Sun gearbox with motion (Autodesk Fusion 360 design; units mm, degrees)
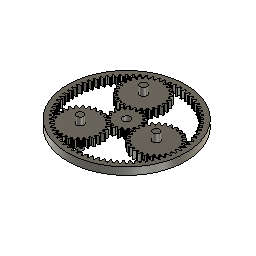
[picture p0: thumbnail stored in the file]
description: Spur Gear; Module: 2.0; Num Teeth: 72; Pressure Angle: 20.0; Backlash: 0.20 mm
description: Spur Gear; Module: 2.0; Num Teeth: 27; Pressure Angle: 20.0; Backlash: 0.20 mm
description: Spur Gear; Module: 2.0; Num Teeth: 18; Pressure Angle: 20.0; Backlash: 0.20 mm
sketch "Base Circle" plane through (0, 0, 0) normal (0, 0, 1) x axis (1, 0, 0)
  circle C1 centre (0, 0) radius 69.686
  circle C2 centre (0, 0) radius 5
extrude "Extrude1" new body sketch "Base Circle" along normal blind 10
sketch "Gear Tooth" plane through (0, 0, 0) normal (0, 0, 1) x axis (1, 0, 0)
  curve K1 (73.9963, -0.7431) -> (67.614, -2.437)
  curve K2 (73.9963, 0.7431) -> (67.614, 2.437)
  line L1 (67.614, -2.437) -> (67.614, 2.437)
  arc A1 centre (0, 0) radius 74 clockwise from (73.9963, 0.7431) to (73.9963, -0.7431)
extrude "Extrude2" add sketch "Gear Tooth" along normal blind 10
fillet "Fillet1" radius 1
circular_pattern "C-Pattern1" countU 72 TotalAngle 360
sketch "Diametrial Pitch Circle" plane through (0, 0, 0) normal (0, 0, 1) x axis (1, 0, 0)
  circle C1 centre (0, 0) radius 72
sketch "Sketch1" plane through (0, 0, 10) normal (0, 0, 1) x axis (-1, 0, 0)
  curve K1 (-69.6244, 2.9297) -> (-70.3744, 2.0033)
  curve K2 (-73.9963, 0.7431) -> (-70.3744, 2.0033)
  curve K3 (-70.3744, -2.0033) -> (-73.9963, -0.7431)
  curve K4 (-70.3744, -2.0033) -> (-69.6244, -2.9297)
  curve K5 (-69.6148, -3.1496) -> (-70.2812, -4.1379)
  curve K6 (-73.7795, -5.709) -> (-70.2812, -4.1379)
  curve K7 (-69.932, -8.1292) -> (-73.6499, -7.1894)
  curve K8 (-69.932, -8.1292) -> (-69.1041, -8.9867)
  curve K9 (-69.0754, -9.2049) -> (-69.6531, -10.2475)
  curve K10 (-73.0011, -12.1176) -> (-69.6531, -10.2475)
  curve K11 (-68.9574, -14.1932) -> (-72.7431, -13.5811)
  curve K12 (-68.9574, -14.1932) -> (-68.0579, -14.9754)
  curve K13 (-68.0103, -15.1902) -> (-68.495, -16.2792)
  curve K14 (-71.6672, -18.4339) -> (-68.495, -16.2792)
  curve K15 (-67.458, -20.1493) -> (-71.2826, -19.8694)
  curve K16 (-67.458, -20.1493) -> (-66.4937, -20.85)
  curve K17 (-66.4275, -21.0599) -> (-66.8155, -22.187)
  curve K18 (-69.7879, -24.61) -> (-66.8155, -22.187)
  curve K19 (-65.4452, -25.9519) -> (-69.2796, -26.0065)
  curve K20 (-65.4452, -25.9519) -> (-64.4235, -26.566)
  curve K21 (-64.3393, -26.7693) -> (-64.6275, -27.9259)
  curve K22 (-67.3774, -30.5987) -> (-64.6275, -27.9259)
  curve K23 (-62.9343, -31.5571) -> (-66.7494, -31.9456)
  curve K24 (-62.9343, -31.5571) -> (-61.863, -32.0798)
  curve K25 (-61.7614, -32.275) -> (-61.9477, -33.4523)
  curve K26 (-64.4542, -36.3546) -> (-61.9477, -33.4523)
  curve K27 (-59.9444, -36.9221) -> (-63.7111, -37.6416)
  curve K28 (-59.9444, -36.9221) -> (-58.8316, -37.3494)
  curve K29 (-58.7134, -37.535) -> (-58.7964, -38.7241)
  curve K30 (-61.0404, -41.8338) -> (-58.7964, -38.7241)
  curve K31 (-56.4983, -42.0061) -> (-60.188, -43.0512)
  curve K32 (-56.4983, -42.0061) -> (-55.3525, -42.3348)
  curve K33 (-55.2186, -42.5094) -> (-55.1976, -43.7012)
  curve K34 (-57.1621, -46.9947) -> (-55.1976, -43.7012)
  curve K35 (-52.6222, -46.7704) -> (-56.2068, -48.1331)
  curve K36 (-52.6222, -46.7704) -> (-51.4522, -46.998)
  curve K37 (-51.3035, -47.1602) -> (-51.1788, -48.3457)
  curve K38 (-52.8487, -51.7978) -> (-51.1788, -48.3457)
  curve K39 (-48.3457, -51.1788) -> (-51.7978, -52.8487)
  curve K40 (-48.3457, -51.1788) -> (-47.1602, -51.3035)
  curve K41 (-46.998, -51.4522) -> (-46.7704, -52.6222)
  curve K42 (-48.1331, -56.2068) -> (-46.7704, -52.6222)
  curve K43 (-43.7012, -55.1976) -> (-46.9947, -57.1621)
  curve K44 (-43.7012, -55.1976) -> (-42.5094, -55.2186)
  curve K45 (-42.3348, -55.3525) -> (-42.0061, -56.4983)
  curve K46 (-43.0512, -60.188) -> (-42.0061, -56.4983)
  curve K47 (-38.7241, -58.7964) -> (-41.8338, -61.0404)
  curve K48 (-38.7241, -58.7964) -> (-37.535, -58.7134)
  curve K49 (-37.3494, -58.8316) -> (-36.9221, -59.9444)
  curve K50 (-37.6416, -63.7111) -> (-36.9221, -59.9444)
  curve K51 (-33.4523, -61.9477) -> (-36.3546, -64.4542)
  curve K52 (-33.4523, -61.9477) -> (-32.275, -61.7614)
  curve K53 (-32.0798, -61.863) -> (-31.5571, -62.9343)
  curve K54 (-31.9456, -66.7494) -> (-31.5571, -62.9343)
  curve K55 (-27.9259, -64.6275) -> (-30.5987, -67.3774)
  curve K56 (-27.9259, -64.6275) -> (-26.7693, -64.3393)
  curve K57 (-26.566, -64.4235) -> (-25.9519, -65.4452)
  curve K58 (-26.0065, -69.2796) -> (-25.9519, -65.4452)
  curve K59 (-22.187, -66.8155) -> (-24.61, -69.7879)
  curve K60 (-22.187, -66.8155) -> (-21.0599, -66.4275)
  curve K61 (-20.85, -66.4937) -> (-20.1493, -67.458)
  curve K62 (-19.8694, -71.2826) -> (-20.1493, -67.458)
  curve K63 (-16.2792, -68.495) -> (-18.4339, -71.6672)
  curve K64 (-16.2792, -68.495) -> (-15.1902, -68.0103)
  curve K65 (-14.9754, -68.0579) -> (-14.1932, -68.9574)
  curve K66 (-13.5811, -72.7431) -> (-14.1932, -68.9574)
  curve K67 (-10.2475, -69.6531) -> (-12.1176, -73.0011)
  curve K68 (-10.2475, -69.6531) -> (-9.2049, -69.0754)
  curve K69 (-8.9867, -69.1041) -> (-8.1292, -69.932)
  curve K70 (-7.1894, -73.6499) -> (-8.1292, -69.932)
  curve K71 (-4.1379, -70.2812) -> (-5.709, -73.7795)
  curve K72 (-4.1379, -70.2812) -> (-3.1496, -69.6148)
  curve K73 (-2.9297, -69.6244) -> (-2.0033, -70.3744)
  curve K74 (-0.7431, -73.9963) -> (-2.0033, -70.3744)
  curve K75 (2.0033, -70.3744) -> (0.7431, -73.9963)
  curve K76 (2.0033, -70.3744) -> (2.9297, -69.6244)
  curve K77 (3.1496, -69.6148) -> (4.1379, -70.2812)
  curve K78 (5.709, -73.7795) -> (4.1379, -70.2812)
  curve K79 (8.1292, -69.932) -> (7.1894, -73.6499)
  curve K80 (8.1292, -69.932) -> (8.9867, -69.1041)
  curve K81 (9.2049, -69.0754) -> (10.2475, -69.6531)
  curve K82 (12.1176, -73.0011) -> (10.2475, -69.6531)
  curve K83 (14.1932, -68.9574) -> (13.5811, -72.7431)
  curve K84 (14.1932, -68.9574) -> (14.9754, -68.0579)
  curve K85 (15.1902, -68.0103) -> (16.2792, -68.495)
  curve K86 (18.4339, -71.6672) -> (16.2792, -68.495)
  curve K87 (20.1493, -67.458) -> (19.8694, -71.2826)
  curve K88 (20.1493, -67.458) -> (20.85, -66.4937)
  curve K89 (21.0599, -66.4275) -> (22.187, -66.8155)
  curve K90 (24.61, -69.7879) -> (22.187, -66.8155)
  curve K91 (25.9519, -65.4452) -> (26.0065, -69.2796)
  curve K92 (25.9519, -65.4452) -> (26.566, -64.4235)
  curve K93 (26.7693, -64.3393) -> (27.9259, -64.6275)
  curve K94 (30.5987, -67.3774) -> (27.9259, -64.6275)
  curve K95 (31.5571, -62.9343) -> (31.9456, -66.7494)
  curve K96 (31.5571, -62.9343) -> (32.0798, -61.863)
  curve K97 (32.275, -61.7614) -> (33.4523, -61.9477)
  curve K98 (36.3546, -64.4542) -> (33.4523, -61.9477)
  curve K99 (36.9221, -59.9444) -> (37.6416, -63.7111)
  curve K100 (36.9221, -59.9444) -> (37.3494, -58.8316)
  curve K101 (37.535, -58.7134) -> (38.7241, -58.7964)
  curve K102 (41.8338, -61.0404) -> (38.7241, -58.7964)
  curve K103 (42.0061, -56.4983) -> (43.0512, -60.188)
  curve K104 (42.0061, -56.4983) -> (42.3348, -55.3525)
  curve K105 (42.5094, -55.2186) -> (43.7012, -55.1976)
  curve K106 (46.9947, -57.1621) -> (43.7012, -55.1976)
  curve K107 (46.7704, -52.6222) -> (48.1331, -56.2068)
  curve K108 (46.7704, -52.6222) -> (46.998, -51.4522)
  curve K109 (47.1602, -51.3035) -> (48.3457, -51.1788)
  curve K110 (51.7978, -52.8487) -> (48.3457, -51.1788)
  curve K111 (51.1788, -48.3457) -> (52.8487, -51.7978)
  curve K112 (51.1788, -48.3457) -> (51.3035, -47.1602)
  curve K113 (51.4522, -46.998) -> (52.6222, -46.7704)
  curve K114 (56.2068, -48.1331) -> (52.6222, -46.7704)
  curve K115 (55.1976, -43.7012) -> (57.1621, -46.9947)
  curve K116 (55.1976, -43.7012) -> (55.2186, -42.5094)
  curve K117 (55.3525, -42.3348) -> (56.4983, -42.0061)
  curve K118 (60.188, -43.0512) -> (56.4983, -42.0061)
  curve K119 (58.7964, -38.7241) -> (61.0404, -41.8338)
  curve K120 (58.7964, -38.7241) -> (58.7134, -37.535)
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  point P1 (0, 0)
  point P435 (0, 0)
  coincident P1 P435
  dimension "d9" diameter = 160
extrude "Extrude1" new body sketch "Sketch1" against normal blind 10
remove_instance "RemoveInstance1"
sketch "Sketch2" plane through (0, 0, 10) normal (0, 0, 1) x axis (-1, 0, 0)
  curve K1 (-70.3744, 2.0033) -> (-73.9963, 0.7431)
  curve K2 (-69.6244, 2.9297) -> (-70.3744, 2.0033)
  curve K3 (-70.2812, 4.1379) -> (-69.6148, 3.1496)
  curve K4 (-73.7795, 5.709) -> (-70.2812, 4.1379)
  curve K5 (-69.932, 8.1292) -> (-73.6499, 7.1894)
  curve K6 (-69.1041, 8.9867) -> (-69.932, 8.1292)
  curve K7 (-69.6531, 10.2475) -> (-69.0754, 9.2049)
  curve K8 (-73.0011, 12.1176) -> (-69.6531, 10.2475)
  curve K9 (-68.9574, 14.1932) -> (-72.7431, 13.5811)
  curve K10 (-68.0579, 14.9754) -> (-68.9574, 14.1932)
  curve K11 (-68.495, 16.2792) -> (-68.0103, 15.1902)
  curve K12 (-71.6672, 18.4339) -> (-68.495, 16.2792)
  curve K13 (-67.458, 20.1493) -> (-71.2826, 19.8694)
  curve K14 (-66.4937, 20.85) -> (-67.458, 20.1493)
  curve K15 (-66.8155, 22.187) -> (-66.4275, 21.0599)
  curve K16 (-69.7879, 24.61) -> (-66.8155, 22.187)
  curve K17 (-65.4452, 25.9519) -> (-69.2796, 26.0065)
  curve K18 (-64.4235, 26.566) -> (-65.4452, 25.9519)
  curve K19 (-64.6275, 27.9259) -> (-64.3393, 26.7693)
  curve K20 (-67.3774, 30.5987) -> (-64.6275, 27.9259)
  curve K21 (-62.9343, 31.5571) -> (-66.7494, 31.9456)
  curve K22 (-61.863, 32.0798) -> (-62.9343, 31.5571)
  curve K23 (-61.9477, 33.4523) -> (-61.7614, 32.275)
  curve K24 (-64.4542, 36.3546) -> (-61.9477, 33.4523)
  curve K25 (-59.9444, 36.9221) -> (-63.7111, 37.6416)
  curve K26 (-58.8316, 37.3494) -> (-59.9444, 36.9221)
  curve K27 (-58.7964, 38.7241) -> (-58.7134, 37.535)
  curve K28 (-61.0404, 41.8338) -> (-58.7964, 38.7241)
  curve K29 (-56.4983, 42.0061) -> (-60.188, 43.0512)
  curve K30 (-55.3525, 42.3348) -> (-56.4983, 42.0061)
  curve K31 (-55.1976, 43.7012) -> (-55.2186, 42.5094)
  curve K32 (-57.1621, 46.9947) -> (-55.1976, 43.7012)
  curve K33 (-52.6222, 46.7704) -> (-56.2068, 48.1331)
  curve K34 (-51.4522, 46.998) -> (-52.6222, 46.7704)
  curve K35 (-51.1788, 48.3457) -> (-51.3035, 47.1602)
  curve K36 (-52.8487, 51.7978) -> (-51.1788, 48.3457)
  curve K37 (-48.3457, 51.1788) -> (-51.7978, 52.8487)
  curve K38 (-47.1602, 51.3035) -> (-48.3457, 51.1788)
  curve K39 (-46.7704, 52.6222) -> (-46.998, 51.4522)
  curve K40 (-48.1331, 56.2068) -> (-46.7704, 52.6222)
  curve K41 (-43.7012, 55.1976) -> (-46.9947, 57.1621)
  curve K42 (-42.5094, 55.2186) -> (-43.7012, 55.1976)
  curve K43 (-42.0061, 56.4983) -> (-42.3348, 55.3525)
  curve K44 (-43.0512, 60.188) -> (-42.0061, 56.4983)
  curve K45 (-38.7241, 58.7964) -> (-41.8338, 61.0404)
  curve K46 (-37.535, 58.7134) -> (-38.7241, 58.7964)
  curve K47 (-36.9221, 59.9444) -> (-37.3494, 58.8316)
  curve K48 (-37.6416, 63.7111) -> (-36.9221, 59.9444)
  curve K49 (-33.4523, 61.9477) -> (-36.3546, 64.4542)
  curve K50 (-32.275, 61.7614) -> (-33.4523, 61.9477)
  curve K51 (-31.5571, 62.9343) -> (-32.0798, 61.863)
  curve K52 (-31.9456, 66.7494) -> (-31.5571, 62.9343)
  curve K53 (-27.9259, 64.6275) -> (-30.5987, 67.3774)
  curve K54 (-26.7693, 64.3393) -> (-27.9259, 64.6275)
  curve K55 (-25.9519, 65.4452) -> (-26.566, 64.4235)
  curve K56 (-26.0065, 69.2796) -> (-25.9519, 65.4452)
  curve K57 (-22.187, 66.8155) -> (-24.61, 69.7879)
  curve K58 (-21.0599, 66.4275) -> (-22.187, 66.8155)
  curve K59 (-20.1493, 67.458) -> (-20.85, 66.4937)
  curve K60 (-19.8694, 71.2826) -> (-20.1493, 67.458)
  curve K61 (-16.2792, 68.495) -> (-18.4339, 71.6672)
  curve K62 (-15.1902, 68.0103) -> (-16.2792, 68.495)
  curve K63 (-14.1932, 68.9574) -> (-14.9754, 68.0579)
  curve K64 (-13.5811, 72.7431) -> (-14.1932, 68.9574)
  curve K65 (-10.2475, 69.6531) -> (-12.1176, 73.0011)
  curve K66 (-9.2049, 69.0754) -> (-10.2475, 69.6531)
  curve K67 (-8.1292, 69.932) -> (-8.9867, 69.1041)
  curve K68 (-7.1894, 73.6499) -> (-8.1292, 69.932)
  curve K69 (-4.1379, 70.2812) -> (-5.709, 73.7795)
  curve K70 (-3.1496, 69.6148) -> (-4.1379, 70.2812)
  curve K71 (-2.0033, 70.3744) -> (-2.9297, 69.6244)
  curve K72 (-0.7431, 73.9963) -> (-2.0033, 70.3744)
  curve K73 (2.0033, 70.3744) -> (0.7431, 73.9963)
  curve K74 (2.9297, 69.6244) -> (2.0033, 70.3744)
  curve K75 (4.1379, 70.2812) -> (3.1496, 69.6148)
  curve K76 (5.709, 73.7795) -> (4.1379, 70.2812)
  curve K77 (8.1292, 69.932) -> (7.1894, 73.6499)
  curve K78 (8.9867, 69.1041) -> (8.1292, 69.932)
  curve K79 (10.2475, 69.6531) -> (9.2049, 69.0754)
  curve K80 (12.1176, 73.0011) -> (10.2475, 69.6531)
  curve K81 (14.1932, 68.9574) -> (13.5811, 72.7431)
  curve K82 (14.9754, 68.0579) -> (14.1932, 68.9574)
  curve K83 (16.2792, 68.495) -> (15.1902, 68.0103)
  curve K84 (18.4339, 71.6672) -> (16.2792, 68.495)
  curve K85 (20.1493, 67.458) -> (19.8694, 71.2826)
  curve K86 (20.85, 66.4937) -> (20.1493, 67.458)
  curve K87 (22.187, 66.8155) -> (21.0599, 66.4275)
  curve K88 (24.61, 69.7879) -> (22.187, 66.8155)
  curve K89 (25.9519, 65.4452) -> (26.0065, 69.2796)
  curve K90 (26.566, 64.4235) -> (25.9519, 65.4452)
  curve K91 (27.9259, 64.6275) -> (26.7693, 64.3393)
  curve K92 (30.5987, 67.3774) -> (27.9259, 64.6275)
  curve K93 (31.5571, 62.9343) -> (31.9456, 66.7494)
  curve K94 (32.0798, 61.863) -> (31.5571, 62.9343)
  curve K95 (33.4523, 61.9477) -> (32.275, 61.7614)
  curve K96 (36.3546, 64.4542) -> (33.4523, 61.9477)
  curve K97 (36.9221, 59.9444) -> (37.6416, 63.7111)
  curve K98 (37.3494, 58.8316) -> (36.9221, 59.9444)
  curve K99 (38.7241, 58.7964) -> (37.535, 58.7134)
  curve K100 (41.8338, 61.0404) -> (38.7241, 58.7964)
  curve K101 (42.0061, 56.4983) -> (43.0512, 60.188)
  curve K102 (42.3348, 55.3525) -> (42.0061, 56.4983)
  curve K103 (43.7012, 55.1976) -> (42.5094, 55.2186)
  curve K104 (46.9947, 57.1621) -> (43.7012, 55.1976)
  curve K105 (46.7704, 52.6222) -> (48.1331, 56.2068)
  curve K106 (46.998, 51.4522) -> (46.7704, 52.6222)
  curve K107 (48.3457, 51.1788) -> (47.1602, 51.3035)
  curve K108 (51.7978, 52.8487) -> (48.3457, 51.1788)
  curve K109 (51.1788, 48.3457) -> (52.8487, 51.7978)
  curve K110 (51.3035, 47.1602) -> (51.1788, 48.3457)
  curve K111 (52.6222, 46.7704) -> (51.4522, 46.998)
  curve K112 (56.2068, 48.1331) -> (52.6222, 46.7704)
  curve K113 (55.1976, 43.7012) -> (57.1621, 46.9947)
  curve K114 (55.2186, 42.5094) -> (55.1976, 43.7012)
  curve K115 (56.4983, 42.0061) -> (55.3525, 42.3348)
  curve K116 (60.188, 43.0512) -> (56.4983, 42.0061)
  curve K117 (58.7964, 38.7241) -> (61.0404, 41.8338)
  curve K118 (58.7134, 37.535) -> (58.7964, 38.7241)
  curve K119 (59.9444, 36.9221) -> (58.8316, 37.3494)
  curve K120 (63.7111, 37.6416) -> (59.9444, 36.9221)
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  point P485 (38.9711, 22.5)
  point P488 (38.9711, 22.5)
  point P487 (-38.9711, 22.5)
  point P489 (-38.9711, 22.5)
  point P486 (0, -45)
  point P490 (0, -45)
  coincident P485 P488
  coincident P487 P489
  coincident P486 P490
  dimension "d12" diameter = 90
sketch "Base Circle" plane through (0, 0, 0) normal (0, 0, 1) x axis (1, 0, 0)
  circle C1 centre (0, 0) radius 24.686
  circle C2 centre (0, 0) radius 5
extrude "Extrude1" new body sketch "Base Circle" along normal blind 10
sketch "Gear Tooth" plane through (0, 0, 0) normal (0, 0, 1) x axis (1, 0, 0)
  curve K1 (28.9922, -0.6738) -> (25.3074, -1.8057)
  curve K2 (28.9922, 0.6738) -> (25.3074, 1.8057)
  line L1 (25.3074, -1.8057) -> (24.6134, -1.7562)
  line L2 (25.3074, 1.8057) -> (24.6134, 1.7562)
  line L3 (24.6134, 1.7562) -> (24.6134, -1.7562)
  arc A1 centre (0, 0) radius 29 clockwise from (28.9922, 0.6738) to (28.9922, -0.6738)
extrude "Extrude2" add sketch "Gear Tooth" along normal blind 10
fillet "Fillet1" radius 1
circular_pattern "C-Pattern1" countU 27 TotalAngle 360
sketch "Diametrial Pitch Circle" plane through (0, 0, 0) normal (0, 0, 1) x axis (1, 0, 0)
  circle C1 centre (0, 0) radius 27
sketch "Base Circle" plane through (0, 0, 0) normal (0, 0, 1) x axis (1, 0, 0)
  circle C1 centre (0, 0) radius 15.686
  circle C2 centre (0, 0) radius 5
extrude "Extrude1" new body sketch "Base Circle" along normal blind 10
sketch "Gear Tooth" plane through (0, 0, 0) normal (0, 0, 1) x axis (1, 0, 0)
  curve K1 (19.9902, -0.626) -> (16.831, -1.6784)
  curve K2 (19.9902, 0.626) -> (16.831, 1.6784)
  line L1 (16.831, -1.6784) -> (15.5986, -1.5555)
  line L2 (16.831, 1.6784) -> (15.5986, 1.5555)
  line L3 (15.5986, 1.5555) -> (15.5986, -1.5555)
  arc A1 centre (0, 0) radius 20 clockwise from (19.9902, 0.626) to (19.9902, -0.626)
extrude "Extrude2" add sketch "Gear Tooth" along normal blind 10
fillet "Fillet1" radius 1
circular_pattern "C-Pattern1" countU 18 TotalAngle 360
sketch "Diametrial Pitch Circle" plane through (0, 0, 0) normal (0, 0, 1) x axis (1, 0, 0)
  circle C1 centre (0, 0) radius 18
component_from_bodies "Body->Comp1"
position "Position1"
copy_paste "CopyPaste1"
copy_paste "CopyPaste2"
position "Position2"
position "Position3"
position "Position4"
position "Position6"
sketch "Sketch3" plane through (0.433, -0.25, 0) normal (0, 0, -1) x axis (1, 0, 0)
  curve K1 (63.1932, 21.0148) -> (64.0774, 21.9582)
  curve K2 (67.5192, 23.2968) -> (64.0774, 21.9582)
  curve K3 (67.4393, 24.642) -> (63.8632, 25.5637)
  curve K4 (63.8632, 25.5637) -> (62.8735, 26.3958)
  curve K5 (62.8135, 26.734) -> (63.4563, 27.8558)
  curve K6 (66.4966, 29.9521) -> (63.4563, 27.8558)
  curve K7 (66.1086, 31.2426) -> (62.4164, 31.3147)
  curve K8 (62.4164, 31.3147) -> (61.2615, 31.8961)
  curve K9 (61.1251, 32.2114) -> (61.4918, 33.4513)
  curve K10 (63.9668, 36.1922) -> (61.4918, 33.4513)
  curve K11 (63.2916, 37.3584) -> (59.6823, 36.5771)
  curve K12 (59.6823, 36.5771) -> (58.4244, 36.8765)
  curve K13 (58.219, 37.1518) -> (58.2899, 38.4428)
  curve K14 (60.066, 41.6806) -> (58.2899, 38.4428)
  curve K15 (59.1402, 42.6597) -> (55.8083, 41.0671)
  curve K16 (55.8083, 41.0671) -> (54.5153, 41.0683)
  curve K17 (54.2519, 41.2888) -> (54.0232, 42.5614)
  curve K18 (55.0047, 46.1215) -> (54.0232, 42.5614)
  curve K19 (53.878, 46.8607) -> (51.0032, 44.5426)
  curve K20 (51.0032, 44.5426) -> (49.7448, 44.2457)
  curve K21 (49.4377, 44.3995) -> (48.9217, 45.585)
  curve K22 (49.0557, 49.2755) -> (48.9217, 45.585)
  curve K23 (47.7889, 49.735) -> (45.5262, 46.8164)
  curve K24 (45.5262, 46.8164) -> (44.3702, 46.2372)
  curve K25 (44.0359, 46.316) -> (43.2603, 47.3506)
  curve K26 (42.5397, 50.9726) -> (43.2603, 47.3506)
  curve K27 (41.2011, 51.1275) -> (39.6724, 47.7658)
  curve K28 (39.6724, 47.7658) -> (38.6812, 46.9356)
  curve K29 (38.3377, 46.9352) -> (37.3445, 47.763)
  curve K30 (35.808, 51.1212) -> (37.3445, 47.763)
  curve K31 (34.4697, 50.9632) -> (33.7575, 47.3396)
  curve K32 (33.7575, 47.3396) -> (32.9844, 46.3032)
  curve K33 (32.6503, 46.2236) -> (31.4929, 46.8001)
  curve K34 (29.2234, 49.7134) -> (31.4929, 46.8001)
  curve K35 (27.9577, 49.251) -> (28.1003, 45.5608)
  curve K36 (28.1003, 45.5608) -> (27.5871, 44.374)
  curve K37 (27.2803, 44.2195) -> (26.0212, 44.5136)
  curve K38 (23.141, 46.8249) -> (26.0212, 44.5136)
  curve K39 (22.016, 46.0832) -> (23.0058, 42.5253)
  curve K40 (23.0058, 42.5253) -> (22.7801, 41.2522)
  curve K41 (22.5172, 41.0311) -> (21.2243, 41.0269)
  curve K42 (17.8886, 42.6117) -> (21.2243, 41.0269)
  curve K43 (16.9651, 41.6305) -> (18.7487, 38.3968)
  curve K44 (18.7487, 38.3968) -> (18.8227, 37.1059)
  curve K45 (18.6179, 36.8302) -> (17.3607, 36.5279)
  curve K46 (13.7495, 37.3008) -> (17.3607, 36.5279)
  curve K47 (13.0771, 36.133) -> (15.5584, 33.3978)
  curve K48 (15.5584, 33.3978) -> (15.9281, 32.1588)
  curve K49 (15.7924, 31.8432) -> (14.6388, 31.2592)
  curve K50 (10.9468, 31.1784) -> (14.6388, 31.2592)
  curve K51 (10.5618, 29.887) -> (13.607, 27.7978)
  curve K52 (13.607, 27.7978) -> (14.2524, 26.6775)
  curve K53 (14.1932, 26.3391) -> (13.2054, 25.5048)
  curve K54 (9.6315, 24.5747) -> (13.2054, 25.5048)
  curve K55 (9.5547, 23.2294) -> (12.9996, 21.8988)
  curve K56 (12.9996, 21.8988) -> (13.886, 20.9574)
  curve K57 (13.9064, 20.6145) -> (13.1377, 19.5749)
  curve K58 (9.8745, 17.8457) -> (13.1377, 19.5749)
  curve K59 (10.1101, 16.519) -> (13.769, 16.0186)
  curve K60 (13.769, 16.0186) -> (14.8486, 15.3071)
  curve K61 (14.9475, 14.9782) -> (14.4392, 13.7892)
  curve K62 (11.6628, 11.3542) -> (14.4392, 13.7892)
  curve K63 (12.198, 10.1175) -> (15.8737, 10.4745)
  curve K64 (15.8737, 10.4745) -> (17.0883, 10.0311)
  curve K65 (17.2604, 9.7338) -> (17.04, 8.4597)
  curve K66 (14.9, 5.45) -> (17.04, 8.4597)
  curve K67 (15.706, 4.3701) -> (19.2002, 5.5651)
  curve K68 (19.2002, 5.5651) -> (20.4843, 5.4138)
  curve K69 (20.7203, 5.1642) -> (20.7998, 3.8736)
  curve K70 (19.4115, 0.4515) -> (20.7998, 3.8736)
  curve K71 (20.4448, -0.4134) -> (23.5693, 1.5552)
  curve K72 (23.5693, 1.5552) -> (24.8537, 1.7041)
  curve K73 (25.1409, 1.5157) -> (25.5158, 0.2782)
  curve K74 (24.9542, -3.3718) -> (25.5158, 0.2782)
  curve K75 (26.1591, -3.9752) -> (28.7453, -1.339)
  curve K76 (28.7453, -1.339) -> (29.9608, -0.8979)
  curve K77 (30.2837, -1.0151) -> (30.9338, -2.1327)
  curve K78 (31.2291, -5.8138) -> (30.9338, -2.1327)
  curve K79 (32.5407, -6.1231) -> (34.4493, -2.9615)
  curve K80 (34.4493, -2.9615) -> (35.5302, -2.2521)
  curve K81 (35.8715, -2.2915) -> (36.7618, -3.2291)
  curve K82 (37.8981, -6.7429) -> (36.7618, -3.2291)
  curve K83 (39.2456, -6.7414) -> (40.3737, -3.2249)
  curve K84 (40.3737, -3.2249) -> (41.2619, -2.2853)
  curve K85 (41.603, -2.245) -> (42.6856, -2.952)
  curve K86 (44.6016, -6.109) -> (42.6856, -2.952)
  curve K87 (45.9124, -5.7967) -> (46.1991, -2.1149)
  curve K88 (46.1991, -2.1149) -> (46.8467, -0.9958)
  curve K89 (47.1693, -0.8779) -> (48.3858, -1.3162)
  curve K90 (50.9782, -3.9463) -> (48.3858, -1.3162)
  curve K91 (52.1817, -3.3401) -> (51.6116, 0.3086)
  curve K92 (51.6116, 0.3086) -> (51.9836, 1.5469)
  curve K93 (52.2704, 1.736) -> (53.5551, 1.5901)
  curve K94 (56.6841, -0.3713) -> (53.5551, 1.5901)
  curve K95 (57.7154, 0.4961) -> (56.3192, 3.915)
  curve K96 (56.3192, 3.915) -> (56.3956, 5.2057)
  curve K97 (56.6311, 5.4558) -> (57.9148, 5.6101)
  curve K98 (61.4118, 4.4232) -> (57.9148, 5.6101)
  curve K99 (62.2153, 5.5051) -> (60.0683, 8.5098)
  curve K100 (60.0683, 8.5098) -> (59.845, 9.7833)
  curve K101 (60.0164, 10.081) -> (61.2299, 10.5272)
  curve K102 (64.9064, 10.1788) -> (61.2299, 10.5272)
  curve K103 (65.4387, 11.4167) -> (62.6566, 13.8454)
  curve K104 (62.6566, 13.8454) -> (62.1456, 15.0331)
  curve K105 (62.2438, 15.3623) -> (63.3217, 16.0763)
  curve K106 (66.9795, 16.5851) -> (63.3217, 16.0763)
  curve K107 (67.2119, 17.9125) -> (63.9448, 19.634)
  curve K108 (63.9448, 19.634) -> (63.1736, 20.6719)
  arc A1 centre (38.5381, 22.25) radius 24.686 clockwise from (63.1932, 21.0148) to (63.1736, 20.6719)
  arc A2 centre (38.5381, 22.25) radius 29 clockwise from (67.4393, 24.642) to (67.5192, 23.2968)
  arc A3 centre (38.5381, 22.25) radius 24.686 clockwise from (62.8135, 26.734) to (62.8735, 26.3958)
  arc A4 centre (38.5381, 22.25) radius 29 clockwise from (66.1086, 31.2426) to (66.4966, 29.9521)
  arc A5 centre (38.5381, 22.25) radius 24.686 clockwise from (61.1251, 32.2114) to (61.2615, 31.8961)
  arc A6 centre (38.5381, 22.25) radius 29 clockwise from (63.2916, 37.3584) to (63.9668, 36.1922)
  arc A7 centre (38.5381, 22.25) radius 24.686 clockwise from (58.219, 37.1518) to (58.4244, 36.8765)
  arc A8 centre (38.5381, 22.25) radius 29 clockwise from (59.1402, 42.6597) to (60.066, 41.6806)
  arc A9 centre (38.5381, 22.25) radius 24.686 clockwise from (54.2519, 41.2888) to (54.5153, 41.0683)
  arc A10 centre (38.5381, 22.25) radius 29 clockwise from (53.878, 46.8607) to (55.0047, 46.1215)
  arc A11 centre (38.5381, 22.25) radius 24.686 clockwise from (49.4377, 44.3995) to (49.7448, 44.2457)
  arc A12 centre (38.5381, 22.25) radius 29 clockwise from (47.7889, 49.735) to (49.0557, 49.2755)
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  dimension "d51" diameter = 9
  dimension "d52" diameter = 9
  dimension "d53" diameter = 9
extrude "Extrude2" new body sketch "Sketch3" distance 20
component_from_bodies "Body->Comp2"
component_from_bodies "Body->Comp3"
component_from_bodies "Body->Comp4"
as_built_joint "As-built12" OffsetX 0 OffsetY 0 OffsetZ 0 AngleZ 0
as_built_joint "As-built6" OffsetX 0 OffsetY 0 OffsetZ 0 AngleZ 0
as_built_joint "As-built7" OffsetX 0 OffsetY 0 OffsetZ 0 AngleZ 0
as_built_joint "As-built8" OffsetX 0 OffsetY 0 OffsetZ 0 AngleZ 0
as_built_joint "As-built9" OffsetX 0 OffsetY 0 OffsetZ 0 AngleZ 0
as_built_joint "As-built10" OffsetX 0 OffsetY 0 OffsetZ 0 AngleZ 0
as_built_joint "As-built11" OffsetX 0 OffsetY 0 OffsetZ 0 AngleZ 0
motion_link "MotionLink12" Value1 360 Value2 192
motion_link "MotionLink13" Value1 360 Value2 192
motion_link "MotionLink14" Value1 360 Value2 192
motion_link "MotionLink8" Value1 360 Value2 960
motion_link "MotionLink9" Value1 360 Value2 960
motion_link "MotionLink11" Value1 360 Value2 960
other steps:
base_feature "Base Feature1"
base_feature "Base Feature1"
base_feature "Base Feature1"
base_feature "Base Feature1"
create_component "CreateComponent1"
create_component "CreateComponent2"
create_component "CreateComponent3"
reparent_decal "ReparentDecal1"
remove_body "RemoveBody1"
create_component "CreateComponent5"
reparent_decal "ReparentDecal2"
remove_body "RemoveBody2"
create_component "CreateComponent6"
reparent_decal "ReparentDecal3"
remove_body "RemoveBody3"
create_component "CreateComponent7"
reparent_decal "ReparentDecal4"
remove_body "RemoveBody4"
create_component "CreateComponent8"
